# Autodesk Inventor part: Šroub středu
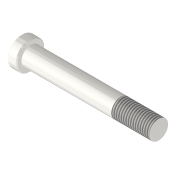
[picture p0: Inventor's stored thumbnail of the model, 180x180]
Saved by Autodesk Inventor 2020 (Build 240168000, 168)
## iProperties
Created: 2025-03
Part Number: Šroub středu
Material: Ocel
Document SubType Name: Modeling
Designer: doma
Density: 7.85 g/cm^3
Appearance: Ocel
Author: doma
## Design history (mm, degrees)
sketch "Náčrt1"
  geometry: L1 (0, 15)-(10, 15); L2 (10, 15)-(10, 10); L3 (10, 10)-(145, 10); L4 (145, 10)-(145, 0); L5 (0, 15)-(0, 0); L6 (0, 0)-(145, 0)
  constraints: 12 end point, 4 perpendicular, 1 horizontal, 1 vertical
  dimensions: "d0" = 10 distance of L1.start L1.end; "d1" = 15 distance of L1.start L5.end; "d2" = 10 distance of L3.end L4.end; "d3" = 135 distance of L2.end L3.end
revolve "Rotace1" sketch "Náčrt1" stored, may be unused: angle "d4" = 90 deg
feature "Závit1" dims "d5" = 40, "d6" = 0
chamfer "Zkosení1" distance "d7" = 1; stored, may be unused: second distance "d8" = 2, angle "d9" = 45 deg
fillet "Zaoblení1" dims "d10" = 0.2
node "Těleso1"
